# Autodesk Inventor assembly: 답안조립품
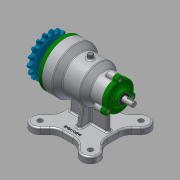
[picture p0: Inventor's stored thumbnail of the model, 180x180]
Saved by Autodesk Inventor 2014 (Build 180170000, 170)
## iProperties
Created: 2017-03
Part Number: 답안조립품
Document SubType Name: Assembly
Designer: SCD-A13
Author: SCD-A13
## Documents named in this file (14)
- C:\Users\SCD-A13\Desktop\470308V1005\답안조립품.iam
- C:\Users\SCD-A13\Desktop\470308V1005\본체.ipt
- C:\Users\SCD-A13\Desktop\470308V1005\뒤커버.ipt
- C:\Users\SCD-A13\Desktop\470308V1005\베어링-6200.ipt
- C:\Users\SCD-A13\Desktop\470308V1005\베어링-6203.ipt
- C:\Users\SCD-A13\Desktop\470308V1005\볼트 M4 x 12.ipt
- C:\Users\SCD-A13\Desktop\470308V1005\볼트 M5 x 10.ipt
- 볼트 M5 x 10.ipt
- C:\Users\SCD-A13\Desktop\470308V1005\스프로킷.ipt
- C:\Users\SCD-A13\Desktop\470308V1005\앞커버.ipt
- C:\Users\SCD-A13\Desktop\470308V1005\오일 실 10 20 7.ipt
- C:\Users\SCD-A13\Desktop\470308V1005\오일 실 17 30 8.ipt
- C:\Users\SCD-A13\Desktop\470308V1005\축.ipt
- C:\Users\SCD-A13\Desktop\470308V1005\키5x5.ipt
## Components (9 placed, 1 different names)
1. ISO 4762 M4 x 12:1
2. ISO 4762 M4 x 12:3
3. ISO 4762 M4 x 12:4
4. ISO 4762 M4 x 12:2
5. ISO 4762 M4 x 12:5
6. ISO 4762 M4 x 12:6
7. ISO 4762 M4 x 12:7
8. ISO 4762 M4 x 12:8
9. ISO 4762 M4 x 12:9
